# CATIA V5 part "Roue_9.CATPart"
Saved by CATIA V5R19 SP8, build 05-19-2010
Part number: Roue_9
Nomenclature: 70_R9
Bounding box of the stored display mesh (mm): x -11.75 to 11.743, y -11.741 to 11.75, z 0 to 1.5
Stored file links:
  C:\Users\rphgr\Desktop\0_Tapis_TC520B_vitesse\Roue_9.CATPart
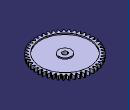
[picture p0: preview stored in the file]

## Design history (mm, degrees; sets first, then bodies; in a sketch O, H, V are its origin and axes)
External parameters (linked from other documents)
  External.Module = 0.5 mm
  External.Z = 45
  External.DiamPrimitif = 22.5 mm {= External.Module *External.Z}
  External.AnglePression = 20 deg
  External.x = 0
  External.DeportDenture = 0 mm {= External.x *External.Module}
  External.DiamBase = 21.1431 mm {= External.DiamPrimitif *cos(External.AnglePression )}
  External.DiamPied = 21.25 mm {= External.DiamPrimitif -2.5*External.Module +2*External.DeportDenture}
  External.DiamTete = 23.5 mm {= External.DiamPrimitif +2*External.Module +2*External.DeportDenture}
  External.PhiPrimitif = 0.854 deg {= atan((sin(External.ThetaPrimitif*1rad)-External.ThetaPrimitif*cos(External.ThetaPrimitif*1rad))/(cos(External.ThetaPrimitif*1rad)+External.ThetaPrimitif*sin(External.ThetaPrimitif*1rad)))}
  External.PhiTete = 1.9168 deg {= atan((sin(External.ThetaTete*1rad)-External.ThetaTete*cos(External.ThetaTete*1rad))/(cos(External.ThetaTete*1rad)+External.ThetaTete*sin(External.ThetaTete*1rad)))}
  External.PhiSymetrie = 2 deg {= 180*1 deg/(2*External.Z )}
  External.CongePied = 0.19 mm {= 0.38*External.Module}
  External.AlphaCopie = 8 deg {= 360*1 deg/External.Z}
  External.AlphaSymetrieCopie = 4 deg {= External.AlphaCopie /2}
  External.CoeffQualiteEngrenage = 7
  External.LargeurDenture = 1.5 mm
  External.ThetaPrimitif = 0.36397 {= sqrt(abs((External.DiamPrimitif*External.DiamPrimitif)/(External.DiamBase *External.DiamBase )-1))}
  External.ThetaTete = 0.485155 {= sqrt(abs((External.DiamTete*External.DiamTete)/(External.DiamBase *External.DiamBase )-1) )}
  External.Di = 21.8215 mm {= (External.DiamBase +External.DiamPrimitif )/2}
  External.Thetai = 0.255358 {= sqrt(abs((External.Di*External.Di)/(External.DiamBase*External.DiamBase)-1))}
  External.Phii = 0.3061 deg {= atan((sin(External.Thetai*1rad)-External.Thetai*cos(External.Thetai*1rad))/(cos(External.Thetai*1rad)+External.Thetai*sin(External.Thetai*1rad)))}
  External.Dj = 23 mm {= (External.DiamTete+External.DiamPrimitif)/2}
  External.Thetaj = 0.428212 {= sqrt(abs((External.Dj*External.Dj)/(External.DiamBase*External.DiamBase)-1))}
  External.Phij = 1.3536 deg {= atan((sin(External.Thetaj*1rad)-External.Thetaj*cos(External.Thetaj*1rad))/(cos(External.Thetaj*1rad)+External.Thetaj*sin(External.Thetaj*1rad)))}
  External.Dk = 21.4823 mm {= (External.Di+External.DiamBase)/2}
  External.Thetak = 0.179851 {= sqrt(abs((External.Dk*External.Dk)/(External.DiamBase*External.DiamBase)-1))}
  External.Phik = 0.109 deg {= atan((sin(External.Thetak*1rad)-External.Thetak*cos(External.Thetak*1rad))/(cos(External.Thetak*1rad)+External.Thetak*sin(External.Thetak*1rad)))}
  External.Dl = 22.1608 mm {= (External.DiamPrimitif+External.Di)/2}
  External.Thetal = 0.31398 {= sqrt(abs((External.Dl*External.Dl)/(External.DiamBase*External.DiamBase)-1))}
  External.Phil = 0.5585 deg {= atan((sin(External.Thetal*1rad)-External.Thetal*cos(External.Thetal*1rad))/(cos(External.Thetal*1rad)+External.Thetal*sin(External.Thetal*1rad)))}
  External.Dm = 22.75 mm {= (External.Dj+External.DiamPrimitif)/2}
  External.Thetam = 0.397216 {= sqrt(abs((External.Dm*External.Dm)/(External.DiamBase*External.DiamBase)-1))}
  External.Phim = 1.095 deg {= atan((sin(External.Thetam*1rad)-External.Thetam*cos(External.Thetam*1rad))/(cos(External.Thetam*1rad)+External.Thetam*sin(External.Thetam*1rad)))}
  External.Dn = 23.25 mm {= (External.DiamTete+External.Dj)/2}
  External.Thetan = 0.457418 {= sqrt(abs((External.Dn*External.Dn)/(External.DiamBase*External.DiamBase)-1))}
  External.Phin = 1.6279 deg {= atan((sin(External.Thetan*1rad)-External.Thetan*cos(External.Thetan*1rad))/(cos(External.Thetan*1rad)+External.Thetan*sin(External.Thetan*1rad)))}
  External.DiametreAlesage = 2 mm
Body1 (main body)
  Sketch1 on xy-plane, origin (0, 0, 0), H (1, 0, 0), V (0, 1, 0)
    construction circle A1 centre (0, 0) radius 11.25
    construction circle A2 centre (0, 0) radius 10.5715
    construction circle A3 centre (0, 0) radius 10.625
    construction circle A4 centre (0, 0) radius 11.75
    point P1 (10.5715, 0)
    construction line L1 (10.5715, 0) -> (0, 0)
    point P2 (11.2488, 0.1677)
    construction line L2 (11.2488, 0.1677) -> (0, 0)
    point P3 (11.7434, 0.393)
    construction line L3 (11.7434, 0.393) -> (0, 0)
    construction line L4 (10.5715, 0) -> (10.5715, 3.9367)
    point P4 (10.5715, 0)
    point P6 (9.8943, 0.1677)
    construction line L5 (11.7434, 0.393) -> (11.2488, 0.1677)
    point P7 (11.4961, 0.2803)
    point P8 (9.647, 0.2803)
    spline S1 through (9.647, 0.2803) (9.8943, 0.1677) (10.5715, 0) (10.7411, 0.0204) (10.9106, 0.0583) (11.0799, 0.108) (11.2488, 0.1677) (11.3729, 0.2174) (11.4968, 0.2717) (11.6203, 0.3302) (11.7434, 0.393)
    construction line L6 (0, 0) -> (5.2679, 0.2626)
    spline S2 through (9.627, 0.6805) (9.862, 0.8172) (10.5191, 1.0514) (10.6899, 1.048) (10.8623, 1.0271) (11.0357, 0.9945) (11.2097, 0.9519) (11.3382, 0.9148) (11.4668, 0.8731) (11.5955, 0.8271) (11.7243, 0.7769)
    arc A5 centre (10.8138, -0.1591) radius 0.19 from (10.7766, 0.0272) to (10.6238, -0.1563) ccw
    point P11 (10.6238, -0.1563)
    arc A6 centre (0, 0) radius 11.75 from (11.7434, 0.393) to (11.7243, 0.7769) ccw
    point P13 (11.7243, 0.7769)
    arc A7 centre (10.7444, 1.2339) radius 0.19 from (10.5556, 1.2122) to (10.7258, 1.0448) ccw
    point P15 (10.5556, 1.2122)
    construction line L7 (0, 0) -> (4.2526, 0.5112)
    construction line L8 (0, 0) -> (5.1248, -0.1025)
    point P19 (10.5491, 1.268)
    arc A8 centre (0, 0) radius 10.625 from (10.5556, 1.2122) to (10.5491, 1.268) ccw
    point P20 (10.6229, -0.2125)
    arc A9 centre (0, 0) radius 10.625 from (10.6229, -0.2125) to (10.6238, -0.1563) ccw
    line L9 (10.5491, 1.268) -> (0, 0)
    line L10 (10.6229, -0.2125) -> (0, 0)
    construction circle A10 centre (0, 0) radius 10.9108
    construction line L11 (0, 0) -> (2.5698, 0.0137)
    point P22 (10.9106, 0.0583)
    construction circle A11 centre (0, 0) radius 11.5
    construction line L12 (0, 0) -> (4.0179, 0.0949)
    point P24 (11.4968, 0.2717)
    point P25 (11.4968, 0.2717)
    point P26 (11.4668, 0.8731)
    point P27 (10.8623, 1.0271)
    construction circle A12 centre (0, 0) radius 10.7412
    construction line L13 (0, 0) -> (48.2618, 0.0918)
    point P29 (10.6899, 1.048)
    construction line L14 (0, 0) -> (63.8991, 3.1855)
    point P31 (10.7411, 0.0204)
    construction circle A13 centre (0, 0) radius 11.0804
    construction line L15 (0, 0) -> (57.3607, 0.5591)
    point P33 (11.0799, 0.108)
    point P34 (11.0357, 0.9945)
    construction circle A14 centre (0, 0) radius 11.375
    construction line L16 (0, 0) -> (65.6987, 1.2558)
    point P36 (11.3729, 0.2174)
    point P37 (11.3382, 0.9148)
    construction circle A15 centre (0, 0) radius 11.625
    axis line L17 (0, 0) -> (59.327, 1.6861)
    point P39 (11.5955, 0.8271)
    point P40 (11.6203, 0.3302)
    point P42 (9.647, 0.2803)
    point P43 (9.8943, 0.1677)
    point P44 (10.5715, 0)
    point P45 (11.2488, 0.1677)
    point P46 (11.7434, 0.393)
    point P47 (11.7243, 0.7769)
    point P48 (9.627, 0.6805)
    point P49 (11.2097, 0.9519)
    point P50 (10.5191, 1.0514)
    point P51 (9.862, 0.8172)
    point P52 (10.9106, 0.0583)
    point P53 (11.4968, 0.2717)
    point P54 (10.8623, 1.0271)
    point P55 (11.4668, 0.8731)
    point P56 (10.7411, 0.0204)
    point P57 (10.6899, 1.048)
    point P58 (11.0799, 0.108)
    point P59 (11.0357, 0.9945)
    point P60 (11.3729, 0.2174)
    point P61 (11.3382, 0.9148)
    point P62 (11.6203, 0.3302)
    point P63 (11.5955, 0.8271)
    radius A1 = 11.25 {= External.DiamPrimitif /2}
    radius A2 = 10.5715 {= External.DiamBase /2}
    radius A3 = 10.625 {= External.DiamPied /2}
    radius A4 = 11.75 {= External.DiamTete /2}
    angle L2 L1 = 0.854 {= External.PhiPrimitif}
    angle L3 L1 = 1.9168 {= External.PhiTete}
    angle L4 L1 = 90
    radius A5 = 0.19 {= External.CongePied}
    radius A7 = 0.19 {= External.CongePied}
    angle L7 L6 = 4 {= External.AlphaSymetrieCopie}
    angle L2 L6 = 2 {= External.PhiSymetrie}
    radius A10 = 10.9108 {= External.Di /2}
    angle L11 L1 = 0.3061 {= External.Phii}
    radius A11 = 11.5 {= External.Dj /2}
    angle L12 L1 = 1.3536 {= External.Phij}
    radius A12 = 10.7412 {= External.Dk/2}
    angle L13 L1 = 0.109 {= External.Phik}
    angle L14 L2 = 2 {= External.PhiSymetrie}
    radius A13 = 11.0804 {= External.Dl /2}
    angle L15 L1 = 0.5585 {= External.Phil}
    radius A14 = 11.375 {= External.Dm /2}
    angle L16 L1 = 1.095 {= External.Phim}
    radius A15 = 11.625 {= External.Dn/2}
    angle L17 L1 = 1.6279 {= External.Phin}
    coincidence: P1 A2, P1 H, P2 A1, P3 A4, P4 A2, P7 L5, P42 P8, P43 P6, P44 P1, P45 L5, P45 L2, P46 L5, P46 L3, P11 A3, P47 P13, P15 A3, P19 L7, P19 A3, P20 L8, P20 A3, P3 P46, P22 L11, P22 A10, P52 P22, P24 L12, P24 A11, P53 P24, P25 P53, P54 P27, P55 P26, P31 L13, P31 A12, P56 P31, P57 P29, P33 L15, P33 A13, P58 P33, P59 P34, P36 L16, P36 A14, P60 P36, P61 P37, P40 L17, P40 A15, P62 P40, P63 P39, O L9, O L10
    horizontal: L1 H
    tangency: L4 A2, A5 A3, A5 S1, A7 A3, A7 S2, A8 A5, A9 A5
    symmetry: P6 P2 L4, P8 P7 L4, P46 P47 L6, P42 P48 L6, P45 P49 L6, P44 P50 L6, P43 P51 L6, L8 L7 L6, P26 P25 L6, P27 P22 L6, P29 P31 L14, P34 P33 L14, P37 P36 L14, P39 P40 L14
    midpoint: P7 L5
    parallelism: L9 L7, L10 L8
    concentricity: A10 A2, A11 A1
  Pad1: profile Sketch1, direction (0, 0, 1), length 1.5 {= External.LargeurDenture}
  CircPattern1 "Roue Dentée": of Pad1, instances 45 {= External.Z}, angular step 8 {= External.AlphaCopie}, axis from Z axis
  Body2
    Sketch2 on xy-plane, origin (0, 0, 0), H (1, 0, 0), V (0, 1, 0)
      circle A1 centre (0, 0) radius 1
      radius A1 = 1 {= External.DiametreAlesage /2}
    Pad2: profile Sketch2, direction (0, 0, 1), length 3 {= 2*External.LargeurDenture}
  Remove1: tool Body2
  Sketch3 on face of CircPattern1, origin (0, 0, 1.5), H (1, 0, 0), V (0, -1, 0)
    circle A1 centre (0, 0) radius 2.5
    circle A2 centre (0, 0) radius 10
    radius A2 = 10
    radius A1 = 2.5
  Pocket1: profile Sketch3, direction (0, 0, -1), length 0.5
